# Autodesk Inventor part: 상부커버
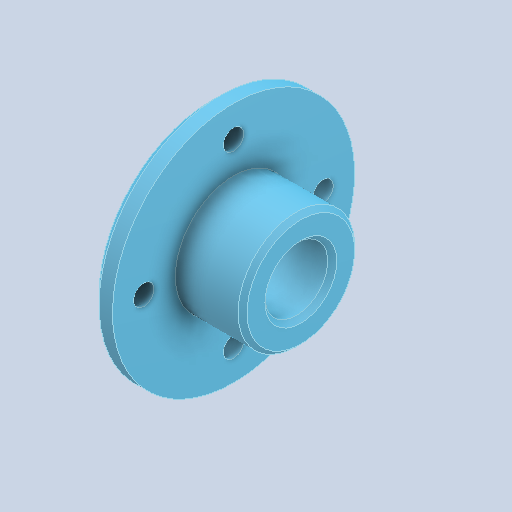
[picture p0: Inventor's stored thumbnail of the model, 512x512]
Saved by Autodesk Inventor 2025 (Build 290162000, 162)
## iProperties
Created: 2025-08
Part Number: 상부커버
Material: 알루미늄 6061
Document SubType Name: Modeling
Designer: infra02
Density: 2.71 g/cm^3
Appearance: 기본값
Author: jhkim
Sending System: Autodesk Inventor 2026
Preprocessor: ST-DEVELOPER v20.1
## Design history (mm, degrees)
feature "솔리드1"
node "솔리드2"
